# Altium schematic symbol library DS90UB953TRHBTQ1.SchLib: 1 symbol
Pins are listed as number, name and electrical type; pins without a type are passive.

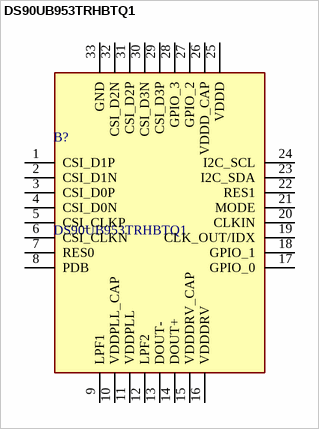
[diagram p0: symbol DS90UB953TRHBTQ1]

## DS90UB953TRHBTQ1
designator B?
2 MP MIPI CSI-2 FPD-Link III serializer for 2MP/60fps cameras & radar; Manufacturer_Name: Texas Instruments; Geometry.Height: 1mm
footprint QFN50P500X500X100-33N-D
pins: 1 CSI_D1P, 2 CSI_D1N, 3 CSI_D0P, 4 CSI_D0N, 5 CSI_CLKP, 6 CSI_CLKN, 7 RES0, 8 PDB, 9 LPF1, 10 VDDPLL_CAP, 11 VDDPLL, 12 LPF2, 13 DOUT-, 14 DOUT+, 15 VDDDRV_CAP, 16 VDDDRV, 17 GPIO_0, 18 GPIO_1, 19 CLK_OUT/IDX, 20 CLKIN, 21 MODE, 22 RES1, 23 I2C_SDA, 24 I2C_SCL, 25 VDDD, 26 VDDD_CAP, 27 GPIO_2, 28 GPIO_3, 29 CSI_D3P, 30 CSI_D3N, 31 CSI_D2P, 32 CSI_D2N, 33 GND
